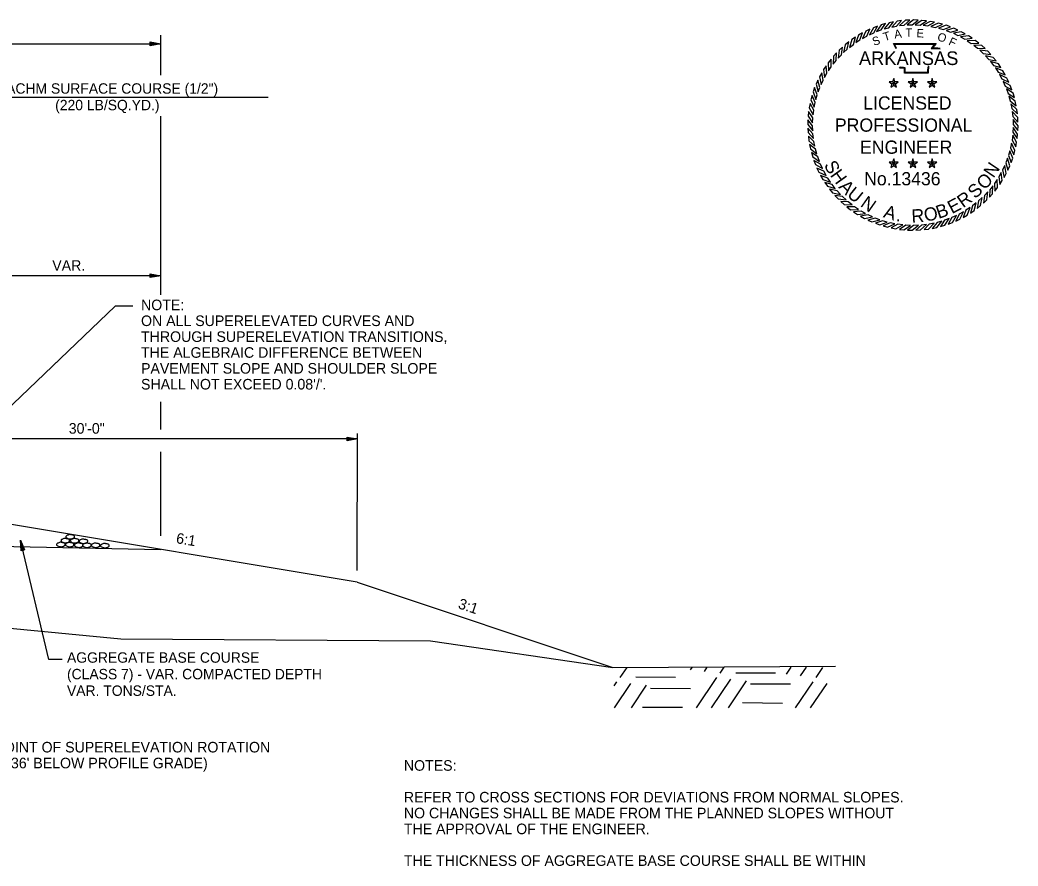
# Model space of a CAD drawing. Extents: x 1001270 to 1003428, y 1840152 to 1842912.
# Drawn here: x 1003371.9 to 1003428.5, y 1842569 to 1842617 of the extents above; entities that cross this region are included whole.
import ezdxf

# ---------------------------------------------------------------- set-up
doc = ezdxf.new("R2010")
doc.units = 0
for name, color, linetype in [('1', 7, 'Continuous'), ('19', 7, 'Continuous'), ('G-ANNO-SYMB', 7, 'Continuous')]:
    doc.layers.add(name, color=color, linetype=linetype)

# ---------------------------------------------------------------- blocks, each defined once
blk = doc.blocks.new('ROCKS')
at = {"layer": '1'}
blk.add_spline([(0.013, 0.06), (0.053, 0.053), (0.107, 0.033), (0.133, 0.013), (0.133, -0.007), (0.12, -0.033), (0.107, -0.04), (0.073, -0.053), (0.033, -0.067), (0.013, -0.067), (-0.02, -0.06), (-0.06, -0.053), (-0.087, -0.047), (-0.113, -0.02), (-0.113, -0.007), (-0.107, 0.02), (-0.087, 0.033), (-0.067, 0.047), (-0.033, 0.053), (-0.02, 0.06), (0.013, 0.06)], degree=3, dxfattribs=at)
blk = doc.blocks.new('4TO1 ABC')
at = {"layer": '1', "xscale": 0.1312491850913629, "yscale": 0.1312491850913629, "rotation": 180}
for p in [(0.00175, -0.00875), (-0.03325, -0.0385), (-0.016625, -0.023625), (0, -0.0385), (0.018375, -0.023625), (0.034125, -0.04025), (0.051625, -0.025375), (0.06475, -0.04025), (0.098, -0.04025), (0.133, -0.041125)]:
    blk.add_blockref('ROCKS', p, dxfattribs=at)

msp = doc.modelspace()

# ---------------------------------------------------------------- linework, layer by layer
at = {"layer": '19'}
for p, q in [((1003379.846, 1842613.871), (1003379.846, 1842616.145)), ((1003307.352, 1842615.645), (1003379.846, 1842615.645)), ((1003379.246, 1842615.54), (1003379.246, 1842615.75)), ((1003379.246, 1842615.75), (1003379.846, 1842615.645)), ((1003379.246, 1842615.695), (1003379.686, 1842615.66)), ((1003379.846, 1842615.645), (1003379.246, 1842615.54)), ((1003379.686, 1842615.63), (1003379.246, 1842615.59)), ((1003300.045, 1842612.618), (1003385.942, 1842612.618)), ((1003379.846, 1842601.394), (1003379.846, 1842611.532)), ((1003379.846, 1842602.488), (1003368.992, 1842602.488)), ((1003379.246, 1842602.383), (1003379.246, 1842602.593)), ((1003379.246, 1842602.593), (1003379.846, 1842602.488)), ((1003379.246, 1842602.538), (1003379.686, 1842602.503)), ((1003379.846, 1842602.488), (1003379.246, 1842602.383)), ((1003379.686, 1842602.473), (1003379.246, 1842602.433)), ((1003377.255, 1842600.764), (1003369.786, 1842593.614)), ((1003378.263, 1842600.764), (1003377.255, 1842600.764)), ((1003379.846, 1842593.755), (1003379.846, 1842595.337)), ((1003390.409, 1842593.115), (1003390.409, 1842593.325)), ((1003390.409, 1842593.325), (1003391.009, 1842593.221)), ((1003390.409, 1842593.27), (1003390.849, 1842593.236)), ((1003390.985, 1842585.755), (1003391.01, 1842593.541)), ((1003391.009, 1842593.221), (1003361.009, 1842593.221)), ((1003391.009, 1842593.221), (1003390.409, 1842593.115)), ((1003390.849, 1842593.206), (1003390.409, 1842593.165)), ((1003379.846, 1842587.732), (1003379.846, 1842592.5)), ((1003390.992, 1842585.091), (1003368.992, 1842588.758)), ((1003362.992, 1842587.286), (1003379.846, 1842586.949)), ((1003373.482, 1842580.714), (1003371.877, 1842587.486)), ((1003371.914, 1842586.88), (1003371.877, 1842587.486)), ((1003371.877, 1842587.486), (1003372.117, 1842586.926)), ((1003371.962, 1842586.891), (1003371.898, 1842587.327)), ((1003371.926, 1842587.334), (1003372.065, 1842586.917)), ((1003372.117, 1842586.926), (1003371.914, 1842586.88)), ((1003390.992, 1842585.091), (1003405.497, 1842580.256)), ((1003374.249, 1842580.714), (1003373.482, 1842580.714)), ((1003405.906, 1842579.678), (1003406.298, 1842580.261)), ((1003409.891, 1842580.112), (1003409.997, 1842580.262)), ((1003410.686, 1842580.02), (1003410.852, 1842580.264)), ((1003411.581, 1842579.928), (1003411.807, 1842580.267)), ((1003415.345, 1842579.872), (1003415.607, 1842580.268)), ((1003416.14, 1842579.781), (1003416.472, 1842580.269)), ((1003417.035, 1842579.688), (1003417.416, 1842580.262)), ((1003406.794, 1842579.717), (1003409.054, 1842579.696)), ((1003410.243, 1842577.965), (1003411.395, 1842579.686)), ((1003412.469, 1842579.957), (1003414.73, 1842579.946)), ((1003405.566, 1842579.21), (1003405.72, 1842579.435)), ((1003405.588, 1842577.961), (1003406.515, 1842579.344)), ((1003406.544, 1842577.963), (1003407.41, 1842579.251)), ((1003411.098, 1842577.967), (1003412.19, 1842579.594)), ((1003412.053, 1842577.969), (1003413.085, 1842579.502)), ((1003413.299, 1842579.329), (1003415.57, 1842579.317)), ((1003415.853, 1842577.97), (1003416.85, 1842579.446)), ((1003416.708, 1842577.973), (1003417.644, 1842579.354)), ((1003407.634, 1842579.088), (1003409.894, 1842579.066)), ((1003407.182, 1842578.008), (1003409.452, 1842577.996)), ((1003412.857, 1842578.259), (1003415.117, 1842578.237))]:
    msp.add_line(p, q, dxfattribs=at)
msp.add_lwpolyline([(1003353.315, 1842584.835), (1003359.249, 1842584.94), (1003366.621, 1842583.111), (1003371.093, 1842582.508), (1003377.579, 1842581.882), (1003395.136, 1842581.764), (1003405.497, 1842580.256), (1003418.132, 1842580.326)], dxfattribs=at)
at = {"layer": 'G-ANNO-SYMB'}
for points in [[(1003420.513, 1842616.653), (1003420.273, 1842616.561), (1003420.048, 1842616.163), (1003420.3, 1842616.278)], [(1003420.96, 1842616.793), (1003420.714, 1842616.72), (1003420.458, 1842616.341), (1003420.719, 1842616.435)], [(1003421.416, 1842616.897), (1003421.165, 1842616.844), (1003420.881, 1842616.487), (1003421.148, 1842616.56)], [(1003421.88, 1842616.966), (1003421.625, 1842616.933), (1003421.314, 1842616.598), (1003421.586, 1842616.65)], [(1003422.347, 1842616.997), (1003422.091, 1842616.984), (1003421.754, 1842616.676), (1003422.029, 1842616.706)], [(1003422.816, 1842616.992), (1003422.559, 1842617), (1003422.199, 1842616.718), (1003422.476, 1842616.727)], [(1003423.282, 1842616.951), (1003423.027, 1842616.978), (1003422.646, 1842616.726), (1003422.923, 1842616.713)], [(1003423.744, 1842616.872), (1003423.492, 1842616.92), (1003423.092, 1842616.698), (1003423.367, 1842616.663)], [(1003424.198, 1842616.758), (1003423.951, 1842616.825), (1003423.535, 1842616.635), (1003423.806, 1842616.579)], [(1003424.642, 1842616.609), (1003424.401, 1842616.695), (1003423.971, 1842616.538), (1003424.237, 1842616.461)], [(1003425.073, 1842616.425), (1003424.839, 1842616.53), (1003424.398, 1842616.407), (1003424.658, 1842616.31)], [(1003419.256, 1842616.029), (1003419.045, 1842615.885), (1003418.919, 1842615.445), (1003419.138, 1842615.615)], [(1003419.658, 1842616.27), (1003419.436, 1842616.142), (1003419.276, 1842615.714), (1003419.507, 1842615.866)], [(1003420.078, 1842616.478), (1003419.846, 1842616.368), (1003419.653, 1842615.954), (1003419.896, 1842616.087)], [(1003425.488, 1842616.208), (1003425.263, 1842616.331), (1003424.814, 1842616.243), (1003425.065, 1842616.125)], [(1003425.885, 1842615.959), (1003425.67, 1842616.099), (1003425.216, 1842616.047), (1003425.457, 1842615.91)], [(1003418.515, 1842615.458), (1003418.329, 1842615.282), (1003418.273, 1842614.828), (1003418.462, 1842615.03)], [(1003418.874, 1842615.758), (1003418.675, 1842615.597), (1003418.584, 1842615.149), (1003418.789, 1842615.336)], [(1003426.261, 1842615.679), (1003426.058, 1842615.836), (1003425.601, 1842615.82), (1003425.83, 1842615.664)], [(1003426.614, 1842615.371), (1003426.424, 1842615.543), (1003425.967, 1842615.563), (1003426.183, 1842615.39)], [(1003418.18, 1842615.13), (1003418.008, 1842614.94), (1003417.988, 1842614.483), (1003418.161, 1842614.699)], [(1003426.942, 1842615.036), (1003426.765, 1842615.223), (1003426.312, 1842615.279), (1003426.514, 1842615.089)], [(1003427.242, 1842614.677), (1003427.081, 1842614.877), (1003426.633, 1842614.968), (1003426.82, 1842614.763)], [(1003417.593, 1842614.401), (1003417.453, 1842614.186), (1003417.504, 1842613.732), (1003417.642, 1842613.973)], [(1003417.872, 1842614.777), (1003417.716, 1842614.574), (1003417.732, 1842614.117), (1003417.887, 1842614.346)], [(1003427.513, 1842614.295), (1003427.368, 1842614.507), (1003426.929, 1842614.633), (1003427.099, 1842614.414)], [(1003427.754, 1842613.893), (1003427.626, 1842614.116), (1003427.198, 1842614.276), (1003427.35, 1842614.044)], [(1003417.344, 1842614.004), (1003417.221, 1842613.779), (1003417.308, 1842613.33), (1003417.426, 1842613.581)], [(1003421.427, 1842613.409), (1003421.488, 1842613.494), (1003421.427, 1842613.682), (1003421.366, 1842613.494)], [(1003422.518, 1842613.409), (1003422.579, 1842613.494), (1003422.518, 1842613.682), (1003422.456, 1842613.494)], [(1003423.609, 1842613.409), (1003423.67, 1842613.494), (1003423.609, 1842613.682), (1003423.547, 1842613.494)], [(1003427.962, 1842613.473), (1003427.852, 1842613.705), (1003427.438, 1842613.899), (1003427.571, 1842613.656)], [(1003416.943, 1842613.158), (1003416.857, 1842612.917), (1003417.013, 1842612.487), (1003417.09, 1842612.753)], [(1003417.127, 1842613.589), (1003417.022, 1842613.355), (1003417.144, 1842612.914), (1003417.242, 1842613.174)], [(1003421.427, 1842613.409), (1003421.366, 1842613.494), (1003421.167, 1842613.494), (1003421.328, 1842613.377)], [(1003421.427, 1842613.409), (1003421.328, 1842613.377), (1003421.266, 1842613.189), (1003421.427, 1842613.305)], [(1003421.427, 1842613.409), (1003421.526, 1842613.377), (1003421.686, 1842613.494), (1003421.488, 1842613.494)], [(1003421.427, 1842613.409), (1003421.427, 1842613.305), (1003421.587, 1842613.189), (1003421.526, 1842613.377)], [(1003422.518, 1842613.409), (1003422.456, 1842613.494), (1003422.258, 1842613.494), (1003422.419, 1842613.377)], [(1003422.518, 1842613.409), (1003422.419, 1842613.377), (1003422.357, 1842613.189), (1003422.518, 1842613.305)], [(1003422.518, 1842613.409), (1003422.617, 1842613.377), (1003422.777, 1842613.494), (1003422.579, 1842613.494)], [(1003422.518, 1842613.409), (1003422.518, 1842613.305), (1003422.678, 1842613.189), (1003422.617, 1842613.377)], [(1003423.609, 1842613.409), (1003423.547, 1842613.494), (1003423.349, 1842613.494), (1003423.51, 1842613.377)], [(1003423.609, 1842613.409), (1003423.51, 1842613.377), (1003423.448, 1842613.189), (1003423.609, 1842613.305)], [(1003423.609, 1842613.409), (1003423.708, 1842613.377), (1003423.868, 1842613.494), (1003423.67, 1842613.494)], [(1003423.609, 1842613.409), (1003423.609, 1842613.305), (1003423.769, 1842613.189), (1003423.708, 1842613.377)], [(1003428.137, 1842613.039), (1003428.045, 1842613.279), (1003427.647, 1842613.504), (1003427.761, 1842613.251)], [(1003428.277, 1842612.592), (1003428.204, 1842612.838), (1003427.825, 1842613.094), (1003427.919, 1842612.833)], [(1003416.793, 1842612.714), (1003416.726, 1842612.467), (1003416.916, 1842612.051), (1003416.972, 1842612.322)], [(1003428.381, 1842612.135), (1003428.328, 1842612.386), (1003427.97, 1842612.671), (1003428.044, 1842612.404)], [(1003416.679, 1842612.26), (1003416.632, 1842612.008), (1003416.854, 1842611.608), (1003416.888, 1842611.883)], [(1003428.449, 1842611.672), (1003428.417, 1842611.926), (1003428.082, 1842612.238), (1003428.134, 1842611.966)], [(1003416.601, 1842611.798), (1003416.574, 1842611.543), (1003416.826, 1842611.162), (1003416.839, 1842611.439)], [(1003428.481, 1842611.204), (1003428.468, 1842611.461), (1003428.159, 1842611.798), (1003428.19, 1842611.522)], [(1003416.559, 1842611.332), (1003416.552, 1842611.075), (1003416.833, 1842610.715), (1003416.825, 1842610.992)], [(1003416.554, 1842610.863), (1003416.567, 1842610.607), (1003416.876, 1842610.27), (1003416.845, 1842610.545)], [(1003428.434, 1842610.269), (1003428.462, 1842610.524), (1003428.209, 1842610.906), (1003428.196, 1842610.629)], [(1003428.476, 1842610.736), (1003428.483, 1842610.992), (1003428.202, 1842611.353), (1003428.211, 1842611.076)], [(1003416.586, 1842610.396), (1003416.619, 1842610.142), (1003416.953, 1842609.83), (1003416.901, 1842610.102)], [(1003428.356, 1842609.807), (1003428.404, 1842610.06), (1003428.182, 1842610.46), (1003428.147, 1842610.185)], [(1003416.654, 1842609.933), (1003416.707, 1842609.681), (1003417.065, 1842609.397), (1003416.992, 1842609.664)], [(1003428.242, 1842609.353), (1003428.309, 1842609.601), (1003428.119, 1842610.017), (1003428.063, 1842609.745)], [(1003416.759, 1842609.476), (1003416.831, 1842609.23), (1003417.21, 1842608.974), (1003417.116, 1842609.235)], [(1003427.909, 1842608.478), (1003428.013, 1842608.713), (1003427.891, 1842609.153), (1003427.793, 1842608.894)], [(1003428.092, 1842608.909), (1003428.179, 1842609.151), (1003428.022, 1842609.581), (1003427.945, 1842609.314)], [(1003416.899, 1842609.029), (1003416.99, 1842608.789), (1003417.388, 1842608.564), (1003417.274, 1842608.817)], [(1003417.073, 1842608.594), (1003417.183, 1842608.362), (1003417.598, 1842608.169), (1003417.464, 1842608.412)], [(1003421.427, 1842608.841), (1003421.366, 1842608.926), (1003421.167, 1842608.926), (1003421.328, 1842608.809)], [(1003421.427, 1842608.841), (1003421.328, 1842608.809), (1003421.266, 1842608.621), (1003421.427, 1842608.737)], [(1003421.427, 1842608.841), (1003421.488, 1842608.926), (1003421.427, 1842609.114), (1003421.366, 1842608.926)], [(1003421.427, 1842608.841), (1003421.526, 1842608.809), (1003421.686, 1842608.926), (1003421.488, 1842608.926)], [(1003421.427, 1842608.841), (1003421.427, 1842608.737), (1003421.587, 1842608.621), (1003421.526, 1842608.809)], [(1003422.518, 1842608.841), (1003422.456, 1842608.926), (1003422.258, 1842608.926), (1003422.419, 1842608.809)], [(1003422.518, 1842608.841), (1003422.419, 1842608.809), (1003422.357, 1842608.621), (1003422.518, 1842608.737)], [(1003422.518, 1842608.841), (1003422.579, 1842608.926), (1003422.518, 1842609.114), (1003422.456, 1842608.926)], [(1003422.518, 1842608.841), (1003422.617, 1842608.809), (1003422.777, 1842608.926), (1003422.579, 1842608.926)], [(1003422.518, 1842608.841), (1003422.518, 1842608.737), (1003422.678, 1842608.621), (1003422.617, 1842608.809)], [(1003423.609, 1842608.841), (1003423.547, 1842608.926), (1003423.349, 1842608.926), (1003423.51, 1842608.809)], [(1003423.609, 1842608.841), (1003423.51, 1842608.809), (1003423.448, 1842608.621), (1003423.609, 1842608.737)], [(1003423.609, 1842608.841), (1003423.67, 1842608.926), (1003423.609, 1842609.114), (1003423.547, 1842608.926)], [(1003423.609, 1842608.841), (1003423.708, 1842608.809), (1003423.868, 1842608.926), (1003423.67, 1842608.926)], [(1003423.609, 1842608.841), (1003423.609, 1842608.737), (1003423.769, 1842608.621), (1003423.708, 1842608.809)], [(1003427.691, 1842608.063), (1003427.814, 1842608.288), (1003427.727, 1842608.737), (1003427.609, 1842608.487)], [(1003417.282, 1842608.175), (1003417.409, 1842607.952), (1003417.838, 1842607.792), (1003417.685, 1842608.024)], [(1003427.442, 1842607.667), (1003427.583, 1842607.881), (1003427.531, 1842608.336), (1003427.394, 1842608.095)], [(1003417.522, 1842607.773), (1003417.667, 1842607.561), (1003418.106, 1842607.435), (1003417.936, 1842607.654)], [(1003426.855, 1842606.938), (1003427.027, 1842607.128), (1003427.047, 1842607.585), (1003426.874, 1842607.368)], [(1003427.163, 1842607.29), (1003427.32, 1842607.494), (1003427.304, 1842607.951), (1003427.148, 1842607.721)], [(1003417.793, 1842607.391), (1003417.954, 1842607.191), (1003418.402, 1842607.1), (1003418.216, 1842607.305)], [(1003418.094, 1842607.031), (1003418.27, 1842606.845), (1003418.724, 1842606.789), (1003418.522, 1842606.979)], [(1003426.161, 1842606.309), (1003426.361, 1842606.47), (1003426.452, 1842606.919), (1003426.247, 1842606.732)], [(1003426.52, 1842606.61), (1003426.707, 1842606.786), (1003426.763, 1842607.24), (1003426.573, 1842607.038)], [(1003418.421, 1842606.696), (1003418.612, 1842606.524), (1003419.069, 1842606.504), (1003418.852, 1842606.678)], [(1003418.774, 1842606.388), (1003418.978, 1842606.232), (1003419.435, 1842606.248), (1003419.205, 1842606.403)], [(1003425.377, 1842605.798), (1003425.599, 1842605.925), (1003425.76, 1842606.354), (1003425.528, 1842606.202)], [(1003425.779, 1842606.038), (1003425.991, 1842606.183), (1003426.117, 1842606.623), (1003425.898, 1842606.453)], [(1003419.15, 1842606.109), (1003419.365, 1842605.969), (1003419.82, 1842606.021), (1003419.579, 1842606.158)], [(1003419.547, 1842605.86), (1003419.772, 1842605.737), (1003420.221, 1842605.824), (1003419.97, 1842605.942)], [(1003419.962, 1842605.643), (1003420.196, 1842605.538), (1003420.637, 1842605.66), (1003420.378, 1842605.758)], [(1003424.523, 1842605.415), (1003424.762, 1842605.506), (1003424.988, 1842605.904), (1003424.735, 1842605.79)], [(1003424.957, 1842605.59), (1003425.189, 1842605.699), (1003425.382, 1842606.114), (1003425.14, 1842605.98)], [(1003420.393, 1842605.459), (1003420.635, 1842605.373), (1003421.064, 1842605.529), (1003420.798, 1842605.606)], [(1003420.837, 1842605.309), (1003421.085, 1842605.243), (1003421.501, 1842605.432), (1003421.229, 1842605.488)], [(1003421.291, 1842605.195), (1003421.543, 1842605.148), (1003421.943, 1842605.37), (1003421.668, 1842605.404)], [(1003421.753, 1842605.117), (1003422.008, 1842605.09), (1003422.39, 1842605.342), (1003422.113, 1842605.355)], [(1003422.22, 1842605.075), (1003422.476, 1842605.068), (1003422.837, 1842605.35), (1003422.56, 1842605.341)], [(1003422.688, 1842605.07), (1003422.944, 1842605.083), (1003423.282, 1842605.392), (1003423.006, 1842605.362)], [(1003423.156, 1842605.102), (1003423.41, 1842605.135), (1003423.722, 1842605.469), (1003423.45, 1842605.417)], [(1003423.619, 1842605.17), (1003423.87, 1842605.223), (1003424.155, 1842605.581), (1003423.887, 1842605.508)], [(1003424.076, 1842605.275), (1003424.322, 1842605.347), (1003424.577, 1842605.726), (1003424.317, 1842605.632)]]:
    msp.add_lwpolyline(points, close=True, dxfattribs=at)
for points in [[(1003421.562, 1842615.364), (1003421.423, 1842615.665), (1003423.829, 1842615.666), (1003423.628, 1842615.414), (1003423.792, 1842615.416), (1003423.928, 1842615.418), (1003424.065, 1842615.403)], [(1003421.596, 1842615.38), (1003421.482, 1842615.627), (1003423.75, 1842615.628), (1003423.548, 1842615.375), (1003423.792, 1842615.378), (1003423.926, 1842615.38), (1003424.06, 1842615.365)], [(1003423.45, 1842614.355), (1003423.409, 1842614.322), (1003423.395, 1842614.272), (1003423.382, 1842614.147), (1003423.382, 1842613.981), (1003422.038, 1842613.981), (1003422.038, 1842614.206), (1003422.038, 1842614.255), (1003421.984, 1842614.272), (1003421.793, 1842614.272), (1003421.759, 1842614.324)], [(1003423.426, 1842614.385), (1003423.375, 1842614.344), (1003423.358, 1842614.279), (1003423.344, 1842614.149), (1003423.344, 1842614.019), (1003422.077, 1842614.019), (1003422.077, 1842614.206), (1003422.077, 1842614.284), (1003421.99, 1842614.31), (1003421.813, 1842614.31), (1003421.791, 1842614.345)]]:
    msp.add_lwpolyline(points, dxfattribs=at)

# ---------------------------------------------------------------- block references
at = {"layer": '19', "xscale": 14.999970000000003, "yscale": 14.999970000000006, "rotation": -0.5653128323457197}
msp.add_blockref('4TO1 ABC', (1003374.699, 1842587.796), dxfattribs=at)

# ---------------------------------------------------------------- texts
at = {"layer": '19'}
for s, height, p in [('6\'-0" ACHM SURFACE COURSE (1/2")', 0.59001, (1003369.277, 1842612.816)), ('(220 LB/SQ.YD.)', 0.59001, (1003373.848, 1842611.876)), ('VAR.', 0.6, (1003373.682, 1842602.767)), ('30\'-0"', 0.6, (1003374.618, 1842593.521)), ('NOTES:', 0.6, (1003393.633, 1842574.394)), ('REFER TO CROSS SECTIONS FOR DEVIATIONS FROM NORMAL SLOPES.', 0.6, (1003393.633, 1842572.594)), ('NO CHANGES SHALL BE MADE FROM THE PLANNED SLOPES WITHOUT', 0.6, (1003393.633, 1842571.694)), ('THE APPROVAL OF THE ENGINEER.', 0.6, (1003393.633, 1842570.794)), ('THE THICKNESS OF AGGREGATE BASE COURSE SHALL BE WITHIN', 0.6, (1003393.633, 1842568.994))]:
    msp.add_text(s, height=height, dxfattribs=at).set_placement(p)
for s, height, rotation, p in [('NOTE:', 0.6, 360, (1003378.72, 1842600.529)), ('ON ALL SUPERELEVATED CURVES AND', 0.6, 360, (1003378.72, 1842599.629)), ('THROUGH SUPERELEVATION TRANSITIONS,', 0.6, 360, (1003378.72, 1842598.729)), ('THE ALGEBRAIC DIFFERENCE BETWEEN', 0.6, 360, (1003378.72, 1842597.829)), ('PAVEMENT SLOPE AND SHOULDER SLOPE', 0.6, 360, (1003378.72, 1842596.929)), ("SHALL NOT EXCEED 0.08'/'.", 0.6, 360, (1003378.72, 1842596.029)), ('6:1', 0.6, 350.6077, (1003380.68, 1842587.313)), ('3:1', 0.6, 341.5651, (1003396.67, 1842583.625)), ('AGGREGATE BASE COURSE', 0.59001, 359.9954, (1003374.519, 1842580.524)), ('(CLASS 7) - VAR. COMPACTED DEPTH', 0.59001, 359.9954, (1003374.519, 1842579.584)), ('VAR. TONS/STA.', 0.59001, 359.9954, (1003374.518, 1842578.644)), ('POINT OF SUPERELEVATION ROTATION', 0.6, 359.9954, (1003370.403, 1842575.432)), ("(0.36' BELOW PROFILE GRADE)", 0.6, 359.9954, (1003370.403, 1842574.532))]:
    msp.add_text(s, height=height, rotation=rotation, dxfattribs=at).set_placement(p)
at = {"layer": 'G-ANNO-SYMB'}
for s, height, rotation, p in [('T', 0.475, 1.4789, (1003422.102, 1842616.038)), ('E', 0.475, 356.672, (1003422.709, 1842616.023)), ('S', 0.475, 19.7726, (1003420.309, 1842615.522)), ('T', 0.475, 16.9015, (1003420.912, 1842615.793)), ('A', 0.475, 8.6788, (1003421.489, 1842615.943)), ('O', 0.475, 341.2218, (1003423.862, 1842615.86)), ('F', 0.475, 335.3628, (1003424.501, 1842615.61)), ('ARKANSAS', 0.7747, 360, (1003419.456, 1842614.442)), ('LICENSED', 0.75, 360, (1003419.696, 1842611.913)), ('PROFESSIONAL', 0.75, 360, (1003418.089, 1842610.659)), ('ENGINEER', 0.75, 360, (1003419.518, 1842609.405)), ('S', 0.75, 298.1636, (1003417.45, 1842608.774)), ('N', 0.75, 56.1007, (1003427.092, 1842607.99)), ('H', 0.75, 305.619, (1003417.792, 1842608.186)), ('No.13436', 0.747, 360, (1003419.754, 1842607.617)), ('O', 0.75, 44.7757, (1003426.571, 1842607.315)), ('A', 0.75, 313.4472, (1003418.268, 1842607.502)), ('U', 0.75, 320.9026, (1003418.735, 1842607.013)), ('S', 0.75, 43.4878, (1003426.055, 1842606.818)), ('N', 0.75, 324.9326, (1003419.491, 1842606.454)), ('E', 0.75, 27.8315, (1003424.732, 1842605.976)), ('R', 0.75, 35.6597, (1003425.366, 1842606.308)), ('A', 0.75, 343.0991, (1003420.799, 1842605.811)), ('O', 0.75, 11.4296, (1003423.223, 1842605.546)), ('B', 0.75, 18.885, (1003423.974, 1842605.705)), ('R', 0.75, 3.2287, (1003422.455, 1842605.497)), ('.', 0.75, 351.3, (1003421.536, 1842605.592))]:
    msp.add_text(s, height=height, rotation=rotation, dxfattribs=at).set_placement(p)

doc.saveas('drawing.dxf')
